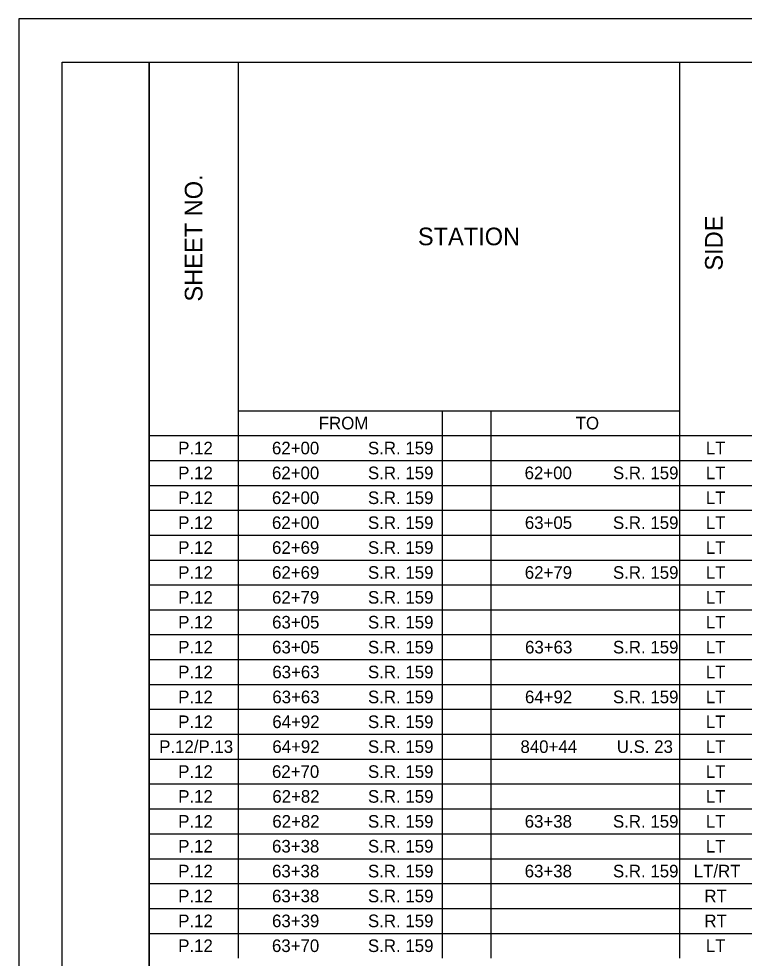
# Model space of a CAD drawing. Extents: x 0 to 34, y 0 to 22.
# Drawn here: x 0 to 8.35, y 11.19 to 22 of the extents above; entities that cross this region are included whole.
import ezdxf

# ---------------------------------------------------------------- set-up
doc = ezdxf.new("R2010")
doc.units = 0
for name, color, linetype in [('Default', 7, 'Continuous'), ('SH_Border', 7, 'Continuous'), ('SH_Cut_Line', 7, 'Continuous')]:
    doc.layers.add(name, color=color, linetype=linetype)

msp = doc.modelspace()

# ---------------------------------------------------------------- linework, layer by layer
at = {"layer": 'Default'}
for p, q in [((1.5, 21.5), (4.873, 21.5)), ((1.5, 21.5), (1.5, 21.214)), ((2.524, 21.5), (2.524, 21.214)), ((4.873, 21.5), (5.433, 21.5)), ((5.433, 21.5), (13.203, 21.5)), ((7.604, 21.5), (7.604, 21.214)), ((1.5, 21.214), (1.5, 20.927)), ((2.524, 21.214), (2.524, 20.927)), ((7.604, 21.214), (7.604, 20.927)), ((1.5, 20.927), (1.5, 20.641)), ((2.524, 20.927), (2.524, 20.641)), ((7.604, 20.927), (7.604, 20.641)), ((1.5, 20.641), (1.5, 20.354)), ((2.524, 20.641), (2.524, 20.354)), ((7.604, 20.641), (7.604, 20.354)), ((1.5, 20.354), (1.5, 20.068)), ((2.524, 20.354), (2.524, 20.068)), ((7.604, 20.354), (7.604, 20.068)), ((1.5, 20.068), (1.5, 19.782)), ((2.524, 20.068), (2.524, 19.782)), ((7.604, 20.068), (7.604, 19.782)), ((1.5, 19.782), (1.5, 19.495)), ((2.524, 19.782), (2.524, 19.495)), ((7.604, 19.782), (7.604, 19.495)), ((1.5, 19.495), (1.5, 19.209)), ((2.524, 19.495), (2.524, 19.209)), ((7.604, 19.495), (7.604, 19.209)), ((1.5, 19.209), (1.5, 18.922)), ((2.524, 19.209), (2.524, 18.922)), ((7.604, 19.209), (7.604, 18.922)), ((1.5, 18.922), (1.5, 18.636)), ((2.524, 18.922), (2.524, 18.636)), ((7.604, 18.922), (7.604, 18.636)), ((1.5, 18.636), (1.5, 18.35)), ((2.524, 18.636), (2.524, 18.35)), ((7.604, 18.636), (7.604, 18.35)), ((1.5, 18.35), (1.5, 18.063)), ((2.524, 18.35), (2.524, 18.063)), ((7.604, 18.35), (7.604, 18.063)), ((1.5, 18.063), (1.5, 17.777)), ((2.524, 18.063), (2.524, 17.777)), ((7.604, 18.063), (7.604, 17.777)), ((1.5, 17.777), (1.5, 17.49)), ((2.524, 17.777), (2.524, 17.49)), ((7.604, 17.777), (7.604, 17.49)), ((1.5, 17.49), (1.5, 17.204)), ((2.524, 17.49), (4.873, 17.49)), ((2.524, 17.49), (2.524, 17.204)), ((4.873, 17.49), (5.433, 17.49)), ((4.873, 17.49), (4.873, 17.204)), ((5.433, 17.49), (7.604, 17.49)), ((5.433, 17.49), (5.433, 17.204)), ((7.604, 17.49), (7.604, 17.204)), ((1.5, 17.204), (4.873, 17.204)), ((1.5, 17.204), (1.5, 16.918)), ((2.524, 17.204), (2.524, 16.918)), ((4.873, 17.204), (5.433, 17.204)), ((4.873, 17.204), (4.873, 16.918)), ((5.433, 17.204), (13.203, 17.204)), ((5.433, 17.204), (5.433, 16.918)), ((7.604, 17.204), (7.604, 16.918)), ((1.5, 16.918), (4.873, 16.918)), ((1.5, 16.918), (1.5, 16.631)), ((2.524, 16.918), (2.524, 16.631)), ((4.873, 16.918), (5.433, 16.918)), ((4.873, 16.918), (4.873, 16.631)), ((5.433, 16.918), (13.203, 16.918)), ((5.433, 16.918), (5.433, 16.631)), ((7.604, 16.918), (7.604, 16.631)), ((1.5, 16.631), (4.873, 16.631)), ((1.5, 16.631), (1.5, 16.345)), ((2.524, 16.631), (2.524, 16.345)), ((4.873, 16.631), (5.433, 16.631)), ((4.873, 16.631), (4.873, 16.345)), ((5.433, 16.631), (13.203, 16.631)), ((5.433, 16.631), (5.433, 16.345)), ((7.604, 16.631), (7.604, 16.345)), ((1.5, 16.345), (4.873, 16.345)), ((1.5, 16.345), (1.5, 16.058)), ((2.524, 16.345), (2.524, 16.058)), ((4.873, 16.345), (5.433, 16.345)), ((4.873, 16.345), (4.873, 16.058)), ((5.433, 16.345), (13.203, 16.345)), ((5.433, 16.345), (5.433, 16.058)), ((7.604, 16.345), (7.604, 16.058)), ((1.5, 16.058), (4.873, 16.058)), ((1.5, 16.058), (1.5, 15.772)), ((2.524, 16.058), (2.524, 15.772)), ((4.873, 16.058), (5.433, 16.058)), ((4.873, 16.058), (4.873, 15.772)), ((5.433, 16.058), (13.203, 16.058)), ((5.433, 16.058), (5.433, 15.772)), ((7.604, 16.058), (7.604, 15.772)), ((1.5, 15.772), (4.873, 15.772)), ((1.5, 15.772), (1.5, 15.486)), ((2.524, 15.772), (2.524, 15.486)), ((4.873, 15.772), (5.433, 15.772)), ((4.873, 15.772), (4.873, 15.486)), ((5.433, 15.772), (13.203, 15.772)), ((5.433, 15.772), (5.433, 15.486)), ((7.604, 15.772), (7.604, 15.486)), ((1.5, 15.486), (4.873, 15.486)), ((1.5, 15.486), (1.5, 15.199)), ((2.524, 15.486), (2.524, 15.199)), ((4.873, 15.486), (5.433, 15.486)), ((4.873, 15.486), (4.873, 15.199)), ((5.433, 15.486), (13.203, 15.486)), ((5.433, 15.486), (5.433, 15.199)), ((7.604, 15.486), (7.604, 15.199)), ((1.5, 15.199), (4.873, 15.199)), ((1.5, 15.199), (1.5, 14.913)), ((2.524, 15.199), (2.524, 14.913)), ((4.873, 15.199), (5.433, 15.199)), ((4.873, 15.199), (4.873, 14.913)), ((5.433, 15.199), (13.203, 15.199)), ((5.433, 15.199), (5.433, 14.913)), ((7.604, 15.199), (7.604, 14.913)), ((1.5, 14.913), (4.873, 14.913)), ((1.5, 14.913), (1.5, 14.626)), ((2.524, 14.913), (2.524, 14.626)), ((4.873, 14.913), (5.433, 14.913)), ((4.873, 14.913), (4.873, 14.626)), ((5.433, 14.913), (13.203, 14.913)), ((5.433, 14.913), (5.433, 14.626)), ((7.604, 14.913), (7.604, 14.626)), ((1.5, 14.626), (4.873, 14.626)), ((1.5, 14.626), (1.5, 14.34)), ((2.524, 14.626), (2.524, 14.34)), ((4.873, 14.626), (5.433, 14.626)), ((4.873, 14.626), (4.873, 14.34)), ((5.433, 14.626), (13.203, 14.626)), ((5.433, 14.626), (5.433, 14.34)), ((7.604, 14.626), (7.604, 14.34)), ((1.5, 14.34), (4.873, 14.34)), ((1.5, 14.34), (1.5, 14.054)), ((2.524, 14.34), (2.524, 14.054)), ((4.873, 14.34), (5.433, 14.34)), ((4.873, 14.34), (4.873, 14.054)), ((5.433, 14.34), (13.203, 14.34)), ((5.433, 14.34), (5.433, 14.054)), ((7.604, 14.34), (7.604, 14.054)), ((1.5, 14.054), (4.873, 14.054)), ((1.5, 14.054), (1.5, 13.767)), ((2.524, 14.054), (2.524, 13.767)), ((4.873, 14.054), (5.433, 14.054)), ((4.873, 14.054), (4.873, 13.767)), ((5.433, 14.054), (13.203, 14.054)), ((5.433, 14.054), (5.433, 13.767)), ((7.604, 14.054), (7.604, 13.767)), ((1.5, 13.767), (4.873, 13.767)), ((1.5, 13.767), (1.5, 13.481)), ((2.524, 13.767), (2.524, 13.481)), ((4.873, 13.767), (5.433, 13.767)), ((4.873, 13.767), (4.873, 13.481)), ((5.433, 13.767), (13.203, 13.767)), ((5.433, 13.767), (5.433, 13.481)), ((7.604, 13.767), (7.604, 13.481)), ((1.5, 13.481), (4.873, 13.481)), ((1.5, 13.481), (1.5, 13.195)), ((2.524, 13.481), (2.524, 13.195)), ((4.873, 13.481), (5.433, 13.481)), ((4.873, 13.481), (4.873, 13.195)), ((5.433, 13.481), (13.203, 13.481)), ((5.433, 13.481), (5.433, 13.195)), ((7.604, 13.481), (7.604, 13.195)), ((1.5, 13.195), (4.873, 13.195)), ((1.5, 13.195), (1.5, 12.908)), ((2.524, 13.195), (2.524, 12.908)), ((4.873, 13.195), (5.433, 13.195)), ((4.873, 13.195), (4.873, 12.908)), ((5.433, 13.195), (13.203, 13.195)), ((5.433, 13.195), (5.433, 12.908)), ((7.604, 13.195), (7.604, 12.908)), ((1.5, 12.908), (4.873, 12.908)), ((1.5, 12.908), (1.5, 12.622)), ((2.524, 12.908), (2.524, 12.622)), ((4.873, 12.908), (5.433, 12.908)), ((4.873, 12.908), (4.873, 12.622)), ((5.433, 12.908), (13.203, 12.908)), ((5.433, 12.908), (5.433, 12.622)), ((7.604, 12.908), (7.604, 12.622)), ((1.5, 12.622), (4.873, 12.622)), ((1.5, 12.622), (1.5, 12.335)), ((2.524, 12.622), (2.524, 12.335)), ((4.873, 12.622), (5.433, 12.622)), ((4.873, 12.622), (4.873, 12.335)), ((5.433, 12.622), (13.203, 12.622)), ((5.433, 12.622), (5.433, 12.335)), ((7.604, 12.622), (7.604, 12.335)), ((1.5, 12.335), (4.873, 12.335)), ((1.5, 12.335), (1.5, 12.049)), ((2.524, 12.335), (2.524, 12.049)), ((4.873, 12.335), (5.433, 12.335)), ((4.873, 12.335), (4.873, 12.049)), ((5.433, 12.335), (13.203, 12.335)), ((5.433, 12.335), (5.433, 12.049)), ((7.604, 12.335), (7.604, 12.049)), ((1.5, 12.049), (4.873, 12.049)), ((1.5, 12.049), (1.5, 11.763)), ((2.524, 12.049), (2.524, 11.763)), ((4.873, 12.049), (5.433, 12.049)), ((4.873, 12.049), (4.873, 11.763)), ((5.433, 12.049), (13.203, 12.049)), ((5.433, 12.049), (5.433, 11.763)), ((7.604, 12.049), (7.604, 11.763)), ((1.5, 11.763), (4.873, 11.763)), ((1.5, 11.763), (1.5, 11.476)), ((2.524, 11.763), (2.524, 11.476)), ((4.873, 11.763), (5.433, 11.763)), ((4.873, 11.763), (4.873, 11.476)), ((5.433, 11.763), (13.203, 11.763)), ((5.433, 11.763), (5.433, 11.476)), ((7.604, 11.763), (7.604, 11.476)), ((1.5, 11.476), (4.873, 11.476)), ((1.5, 11.476), (1.5, 11.19)), ((2.524, 11.476), (2.524, 11.19)), ((4.873, 11.476), (5.433, 11.476)), ((4.873, 11.476), (4.873, 11.19)), ((5.433, 11.476), (13.203, 11.476)), ((5.433, 11.476), (5.433, 11.19)), ((7.604, 11.476), (7.604, 11.19))]:
    msp.add_line(p, q, dxfattribs=at)
at = {"layer": 'SH_Border'}
for points in [[(0.5, 21.5), (1.5, 21.5), (1.5, 0.5), (0.5, 0.5)], [(1.5, 21.5), (33.5, 21.5), (33.5, 0.5), (1.5, 0.5)]]:
    msp.add_lwpolyline(points, close=True, dxfattribs=at)
at = {"layer": 'SH_Cut_Line'}
msp.add_lwpolyline([(0, 0), (34, 0), (34, 22), (0, 22)], close=True, dxfattribs=at)

# ---------------------------------------------------------------- texts
at = {"layer": 'Default'}
for s, p in [('SHEET NO.', (2.114, 18.746)), ('SIDE', (8.102, 19.102))]:
    msp.add_text(s, height=0.2031, rotation=90, dxfattribs=at).set_placement(p)
for s, height, p in [('STATION', 0.2029, (4.594, 19.394)), ('FROM', 0.1449, (3.453, 17.275)), ('TO', 0.1449, (6.41, 17.275)), ('P.12', 0.1449, (1.835, 16.988)), ('62+00', 0.1449, (2.914, 16.988)), ('S.R. 159', 0.1449, (4.019, 16.988)), ('LT', 0.1449, (7.908, 16.988)), ('P.12', 0.1449, (1.835, 16.702)), ('62+00', 0.1449, (2.914, 16.702)), ('S.R. 159', 0.1449, (4.019, 16.702)), ('62+00', 0.1449, (5.822, 16.702)), ('S.R. 159', 0.1449, (6.839, 16.702)), ('LT', 0.1449, (7.908, 16.702)), ('P.12', 0.1449, (1.835, 16.416)), ('62+00', 0.1449, (2.914, 16.416)), ('S.R. 159', 0.1449, (4.019, 16.416)), ('LT', 0.1449, (7.908, 16.416)), ('P.12', 0.1449, (1.835, 16.129)), ('62+00', 0.1449, (2.914, 16.129)), ('S.R. 159', 0.1449, (4.019, 16.129)), ('63+05', 0.1449, (5.825, 16.129)), ('S.R. 159', 0.1449, (6.839, 16.129)), ('LT', 0.1449, (7.908, 16.129)), ('P.12', 0.1449, (1.835, 15.843)), ('62+69', 0.1449, (2.915, 15.843)), ('S.R. 159', 0.1449, (4.019, 15.843)), ('LT', 0.1449, (7.908, 15.843)), ('P.12', 0.1449, (1.835, 15.556)), ('62+69', 0.1449, (2.915, 15.556)), ('S.R. 159', 0.1449, (4.019, 15.556)), ('62+79', 0.1449, (5.824, 15.556)), ('S.R. 159', 0.1449, (6.839, 15.556)), ('LT', 0.1449, (7.908, 15.556)), ('P.12', 0.1449, (1.835, 15.27)), ('62+79', 0.1449, (2.915, 15.27)), ('S.R. 159', 0.1449, (4.019, 15.27)), ('LT', 0.1449, (7.908, 15.27)), ('P.12', 0.1449, (1.835, 14.984)), ('63+05', 0.1449, (2.916, 14.984)), ('S.R. 159', 0.1449, (4.019, 14.984)), ('LT', 0.1449, (7.908, 14.984)), ('P.12', 0.1449, (1.835, 14.697)), ('63+05', 0.1449, (2.916, 14.697)), ('S.R. 159', 0.1449, (4.019, 14.697)), ('63+63', 0.1449, (5.827, 14.697)), ('S.R. 159', 0.1449, (6.839, 14.697)), ('LT', 0.1449, (7.908, 14.697)), ('P.12', 0.1449, (1.835, 14.411)), ('63+63', 0.1449, (2.918, 14.411)), ('S.R. 159', 0.1449, (4.019, 14.411)), ('LT', 0.1449, (7.908, 14.411)), ('P.12', 0.1449, (1.835, 14.124)), ('63+63', 0.1449, (2.918, 14.124)), ('S.R. 159', 0.1449, (4.019, 14.124)), ('64+92', 0.1449, (5.826, 14.124)), ('S.R. 159', 0.1449, (6.839, 14.124)), ('LT', 0.1449, (7.908, 14.124)), ('P.12', 0.1449, (1.835, 13.838)), ('64+92', 0.1449, (2.918, 13.838)), ('S.R. 159', 0.1449, (4.019, 13.838)), ('LT', 0.1449, (7.908, 13.838)), ('P.12/P.13', 0.1449, (1.616, 13.552)), ('64+92', 0.1449, (2.918, 13.552)), ('S.R. 159', 0.1449, (4.019, 13.552)), ('840+44', 0.1449, (5.774, 13.552)), ('U.S. 23', 0.1449, (6.883, 13.552)), ('LT', 0.1449, (7.908, 13.552)), ('P.12', 0.1449, (1.835, 13.265)), ('62+70', 0.1449, (2.914, 13.265)), ('S.R. 159', 0.1449, (4.019, 13.265)), ('LT', 0.1449, (7.908, 13.265)), ('P.12', 0.1449, (1.835, 12.979)), ('62+82', 0.1449, (2.918, 12.979)), ('S.R. 159', 0.1449, (4.019, 12.979)), ('LT', 0.1449, (7.908, 12.979)), ('P.12', 0.1449, (1.835, 12.692)), ('62+82', 0.1449, (2.918, 12.692)), ('S.R. 159', 0.1449, (4.019, 12.692)), ('63+38', 0.1449, (5.823, 12.692)), ('S.R. 159', 0.1449, (6.839, 12.692)), ('LT', 0.1449, (7.908, 12.692)), ('P.12', 0.1449, (1.835, 12.406)), ('63+38', 0.1449, (2.915, 12.406)), ('S.R. 159', 0.1449, (4.019, 12.406)), ('LT', 0.1449, (7.908, 12.406)), ('P.12', 0.1449, (1.835, 12.12)), ('63+38', 0.1449, (2.915, 12.12)), ('S.R. 159', 0.1449, (4.019, 12.12)), ('63+38', 0.1449, (5.823, 12.12)), ('S.R. 159', 0.1449, (6.839, 12.12)), ('LT/RT', 0.1449, (7.769, 12.12)), ('P.12', 0.1449, (1.835, 11.833)), ('63+38', 0.1449, (2.915, 11.833)), ('S.R. 159', 0.1449, (4.019, 11.833)), ('RT', 0.1449, (7.891, 11.833)), ('P.12', 0.1449, (1.835, 11.547)), ('63+39', 0.1449, (2.915, 11.547)), ('S.R. 159', 0.1449, (4.019, 11.547)), ('RT', 0.1449, (7.891, 11.547)), ('P.12', 0.1449, (1.835, 11.261)), ('63+70', 0.1449, (2.914, 11.261)), ('S.R. 159', 0.1449, (4.019, 11.261)), ('LT', 0.1449, (7.908, 11.261))]:
    msp.add_text(s, height=height, dxfattribs=at).set_placement(p)

doc.saveas('drawing.dxf')
